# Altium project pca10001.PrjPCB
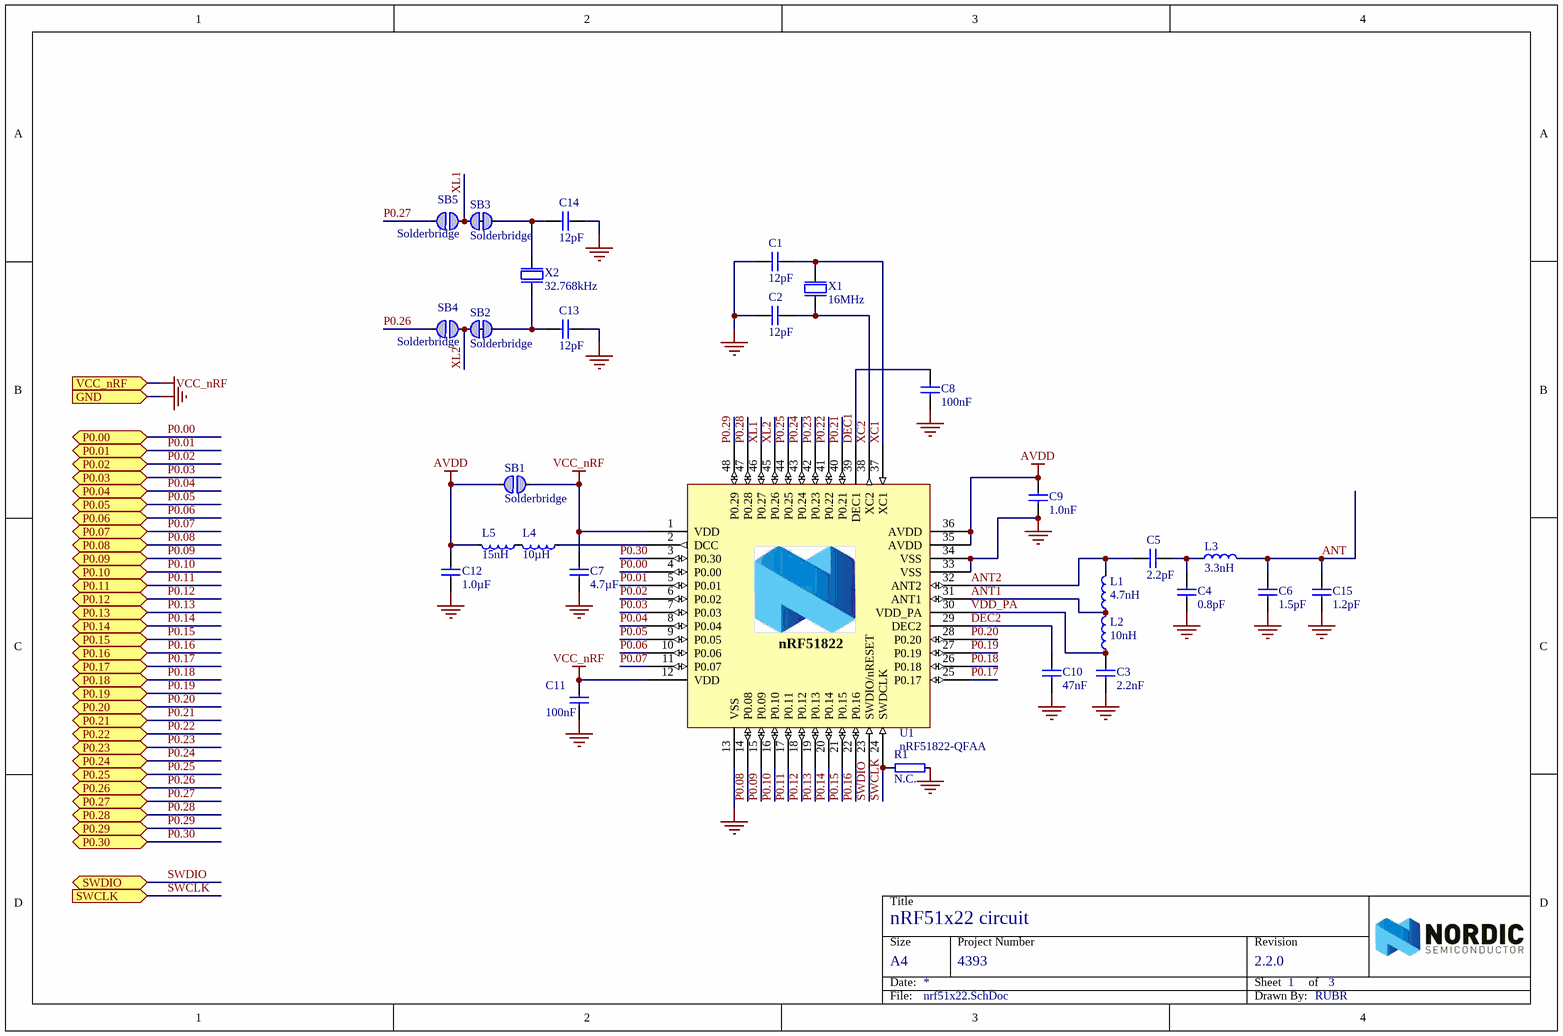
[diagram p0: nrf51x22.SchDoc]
3 sheets, 116 parts. Net scope: flat (ports and power ports of the same name join across sheets).
Board file: 400004.PcbDoc
Sheets:
  nrf51x22.SchDoc
  l-link-ob-sam3u-lqfp.SchDoc
  nrf51x22_ek_interfaces.SchDoc

## Sheet nrf51x22.SchDoc: nRF51x22 circuit
size A4; Revision: 2.2.0; SheetNumber: 1; SheetTotal: 3; DrawnBy: RUBR; ProjectNumber: 4393; PCBRevision: 0101RUBR; DocumentSize: A4; PCAName: PCA10001; PCBNumber: 400004

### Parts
C1  12pF  [CAPC1005X04L]
C2  12pF  [CAPC1005X04L]
C3  2.2nF  [CAPC1005X04L]
C4  0.8pF  [CAPC1005X04L]
C5  2.2pF  [CAPC1005X04L]
C6  1.5pF  [CAPC1005X04L]
C7  4.7µF  [CAPC1608X06L]
C8  100nF  [CAPC1005X04L]
C9  1.0nF  [CAPC1005X04L]
C10  47nF  [CAPC1005X04L]
C11  100nF  [CAPC1005X04L]
C12  1.0µF  [CAPC1608X06L]
C13  12pF  [CAPC1005X04L]
C14  12pF  [CAPC1005X04L]
C15  1.2pF  [CAPC1005X04L]
L1  4.7nH  [INDC1005X04L]
L2  10nH  [INDC1005X04L]
L3  3.3nH  [INDC1005X04L]
L4  10µH  [INDC1608X06L]
L5  15nH  [INDC1005X04L]
R1  N.C.  [RESC1005X04L]
SB1  Solderbridge  [Solderbridge]  (no BOM)
SB2  Solderbridge  [Solderbridge_Shorted]  (net tie, no BOM)
SB3  Solderbridge  [Solderbridge_Shorted]  (net tie, no BOM)
SB4  Solderbridge  [Solderbridge]  (no BOM)
SB5  Solderbridge  [Solderbridge]  (no BOM)
U1  nRF51822-QFAA  [QFN40P600X600X90-48N]
X1  16MHz  [BT-XTAL_2520]
X2  32.768kHz  [FC-135]

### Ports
GND (in), P0.00 (bidir), P0.01 (bidir), P0.02 (bidir), P0.03 (bidir), P0.04 (bidir), P0.05 (bidir), P0.06 (bidir), P0.07 (bidir), P0.08 (bidir), P0.09 (bidir), P0.10 (bidir), P0.11 (bidir), P0.12 (bidir), P0.13 (bidir), P0.14 (bidir), P0.15 (bidir), P0.16 (bidir), P0.17 (bidir), P0.18 (bidir), P0.19 (bidir), P0.20 (bidir), P0.21 (bidir), P0.22 (bidir), P0.23 (bidir), P0.24 (bidir), P0.25 (bidir), P0.26 (bidir), P0.27 (bidir), P0.28 (bidir), P0.29 (bidir), P0.30 (bidir), SWCLK (in), SWDIO (bidir), VCC_nRF (in)

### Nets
AVDD: C9.1 C12.2 L5.2 SB1.2 U1.35(AVDD) U1.36(AVDD)
GND: C1.2 C2.2 C3.2 C4.2 C6.2 C7.2 C8.2 C9.2 C10.2 C11.2 C12.1 C13.2 C14.2 C15.2 R1.1 U1.13(VSS) U1.33(VSS) U1.34(VSS) U1.49 X1.2(GND) X1.4(GND) ; port GND
VCC_nRF: C7.1 C11.1 SB1.1 U1.1(VDD) U1.12(VDD) ; port VCC_nRF
ANT: C6.1 C15.1 L3.2
ANT1: L1.1 L2.2 U1.31(ANT1)
ANT2: C5.1 L1.2 U1.32(ANT2)
DEC1: C8.1 U1.39(DEC1)
DEC2: C10.1 U1.29(DEC2)
P0.00: U1.4(P0.00) ; port P0.00
P0.01: U1.5(P0.01) ; port P0.01
P0.02: U1.6(P0.02) ; port P0.02
P0.03: U1.7(P0.03) ; port P0.03
P0.04: U1.8(P0.04) ; port P0.04
P0.05: U1.9(P0.05) ; port P0.05
P0.06: U1.10(P0.06) ; port P0.06
P0.07: U1.11(P0.07) ; port P0.07
P0.08: U1.14(P0.08) ; port P0.08
P0.09: U1.15(P0.09) ; port P0.09
P0.10: U1.16(P0.10) ; port P0.10
P0.11: U1.17(P0.11) ; port P0.11
P0.12: U1.18(P0.12) ; port P0.12
P0.13: U1.19(P0.13) ; port P0.13
P0.14: U1.20(P0.14) ; port P0.14
P0.15: U1.21(P0.15) ; port P0.15
P0.16: U1.22(P0.16) ; port P0.16  [project net BUTTON0]
P0.17: U1.25(P0.17) ; port P0.17  [project net BUTTON1]
P0.18: U1.26(P0.18) ; port P0.18  [project net LED0]
P0.19: U1.27(P0.19) ; port P0.19  [project net LED1]
P0.20: U1.28(P0.20) ; port P0.20
P0.21: U1.40(P0.21) ; port P0.21
P0.22: U1.41(P0.22) ; port P0.22
P0.23: U1.42(P0.23) ; port P0.23
P0.24: U1.43(P0.24) ; port P0.24
P0.25: U1.44(P0.25) ; port P0.25
P0.26: SB4.2 ; port P0.26
P0.27: SB5.2 ; port P0.27
P0.28: U1.47(P0.28) ; port P0.28
P0.29: U1.48(P0.29) ; port P0.29
P0.30: U1.3(P0.30) ; port P0.30
SWCLK: R1.2 U1.24(SWDCLK) ; port SWCLK
SWDIO: U1.23(SWDIO/nRESET) ; port SWDIO
VDD_PA: C3.1 L2.1 U1.30(VDD_PA)
XC1: C1.1 U1.37(XC1) X1.1(inp)
XC2: C2.1 U1.38(XC2) X1.3(out)
XL1: SB3.2 SB5.1 U1.46(P0.27)
XL2: SB2.2 SB4.1 U1.45(P0.26)
NetC4_1: C4.1 C5.2 L3.1
NetC13_1: C13.1 SB2.1 X2.1(inp)
NetC14_1: C14.1 SB3.1 X2.2(out)
NetL4_1: L4.1 U1.2(DCC)
NetL4_2: L4.2 L5.1

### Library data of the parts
C1 C2 C13 C14 = C0402-12p: Capacitor, NP0, ±2%; Note: 50V; Artikkelnr Noca: 20029159
C3 = C0402-2n2: Capacitor, X7R, ±10%; Note: 50V; Artikkelnr Noca: 20039221
C4 = C0402-0.8p: Capacitor, NP0, ±5%; Note: 50V; Artikkelnr Noca: 20029147
C5 = C0402-2.2p: Capacitor, NP0, ±0.1pF; Note: 50V; Artikkelnr Noca: 20029145
C6 = C0402-1.5p: Capacitor, NP0, ±0.1pF; Note: 50V; Artikkelnr Noca: 20029139
C7 = C0603-4µ7: Capacitor, X5R, ±10%; Note: 6.3V; Artikkelnr Noca: 20069060
C8 C11 = C0402-100n: Capacitor, X7R, ±10%; Note: 16V; Artikkelnr Noca: 20039200
C9 = C0402-1n0: Capacitor, X7R, ±10%; Note: 50V; Artikkelnr Noca: 20039223
C10 = C0402-47n: Capacitor, X7R, ±10%; Note: Chip Cap 10%; Artikkelnr Noca: 20039389
C12 = C0603-1µ0: Capacitor, X7R, ±10%; Note: 16V; Artikkelnr Noca: 20039335
C15 = C0402-1.2p: Capacitor, NP0, ±0.1pF; Note: 50V; Artikkelnr Noca: 20029157
L1 = L0402-4n7: Inductor, 160mA, ±0.1nH; Manufacturer: Murata; Manufacturer Part Number: LQP15MN4N7B02D; Note: High frequency chip inductor ±5%; Artikkelnr Noca: 33029164
L2 = L0402-10n: Inductor, 100mA, ±2%; Manufacturer: Murata; Manufacturer Part Number: LQP15MN10NG02D; Note: High frequency chip inductor ±5%; Artikkelnr Noca: 33029425
L3 = L0402-3n3: Inductor, 190mA, ±0.1nH; Manufacturer: Murata; Manufacturer Part Number: LQP15MN3N3B02D; Note: High frequency chip inductor ±5%; Artikkelnr Noca: 33029369
L4 = L0603-10µ: Inductor, 80mA, ±10%; Manufacturer: Taiyo Yuden; Manufacturer Part Number: LBMF1608T100K; 2nd source part number: 178-6105; Note: LBMF1608T100K 10µH 80mA 0603; Artikkelnr Noca: 33029314
L5 = L0402-15n: Inductor, 320mA, ±5%; Manufacturer: Taiyo Yuden; Manufacturer Part Number: HK100515NJ-T; 2nd source part number: 658-1328; Note: High frequency chip inductor ±10%; Artikkelnr Noca: 33029323
R1 = R0402-N.C.: Not mounted; Note: Chip Res; Artikkelnr Noca: N.A.
SB1 SB4 SB5 = Solderbridge: Artikkelnr Noca: N.A.
SB2 SB3 = Solderbridge Shorted: Shorted Solderbridge; Artikkelnr Noca: N.A.
U1 = nRF51822-QFAA-XLR2.4: Multi-protocol Bluetooth Low Energy and 2.4GHz proprietary system-on-chip; Manufacturer: Nordic Semiconductor; Manufacturer Part Number: nRF51822-QFAAGx; Note: nRF51822 - QFN48 6x6 0.4mm pitch; Artikkelnr Noca: 15079242
X1 = NX2520SA-16MHZ-STD-CSW-5: XTAL SMD 2520, 16MHz, 8pF, ±15ppm; Manufacturer: NDK; Note: XTAL SMD 16.000MHz; Artikkelnr Noca: 22019192
X2 = XTAL_FC-135 32.768k: EPSON TOYOCOM - FC-135 32.768KHZ ±20PPM,9.0PF - CRYSTAL, SM, WATCH; 2nd source part number: 127-8037; Note: XTAL SMD 32.768kHz, 3215; Artikkelnr Noca: 22019091

## Sheet l-link-ob-sam3u-lqfp.SchDoc: J-Link-OB-SAM3U LQPF100
size A3; Revision: 2.0.0; SheetNumber: 2; SheetTotal: 3; DrawnBy: RUBR; ProjectNumber: 4393; PCAName: PCA10001; PCBRevision: 0101RUBR; DocumentSize: A3; PCBNumber: 400004
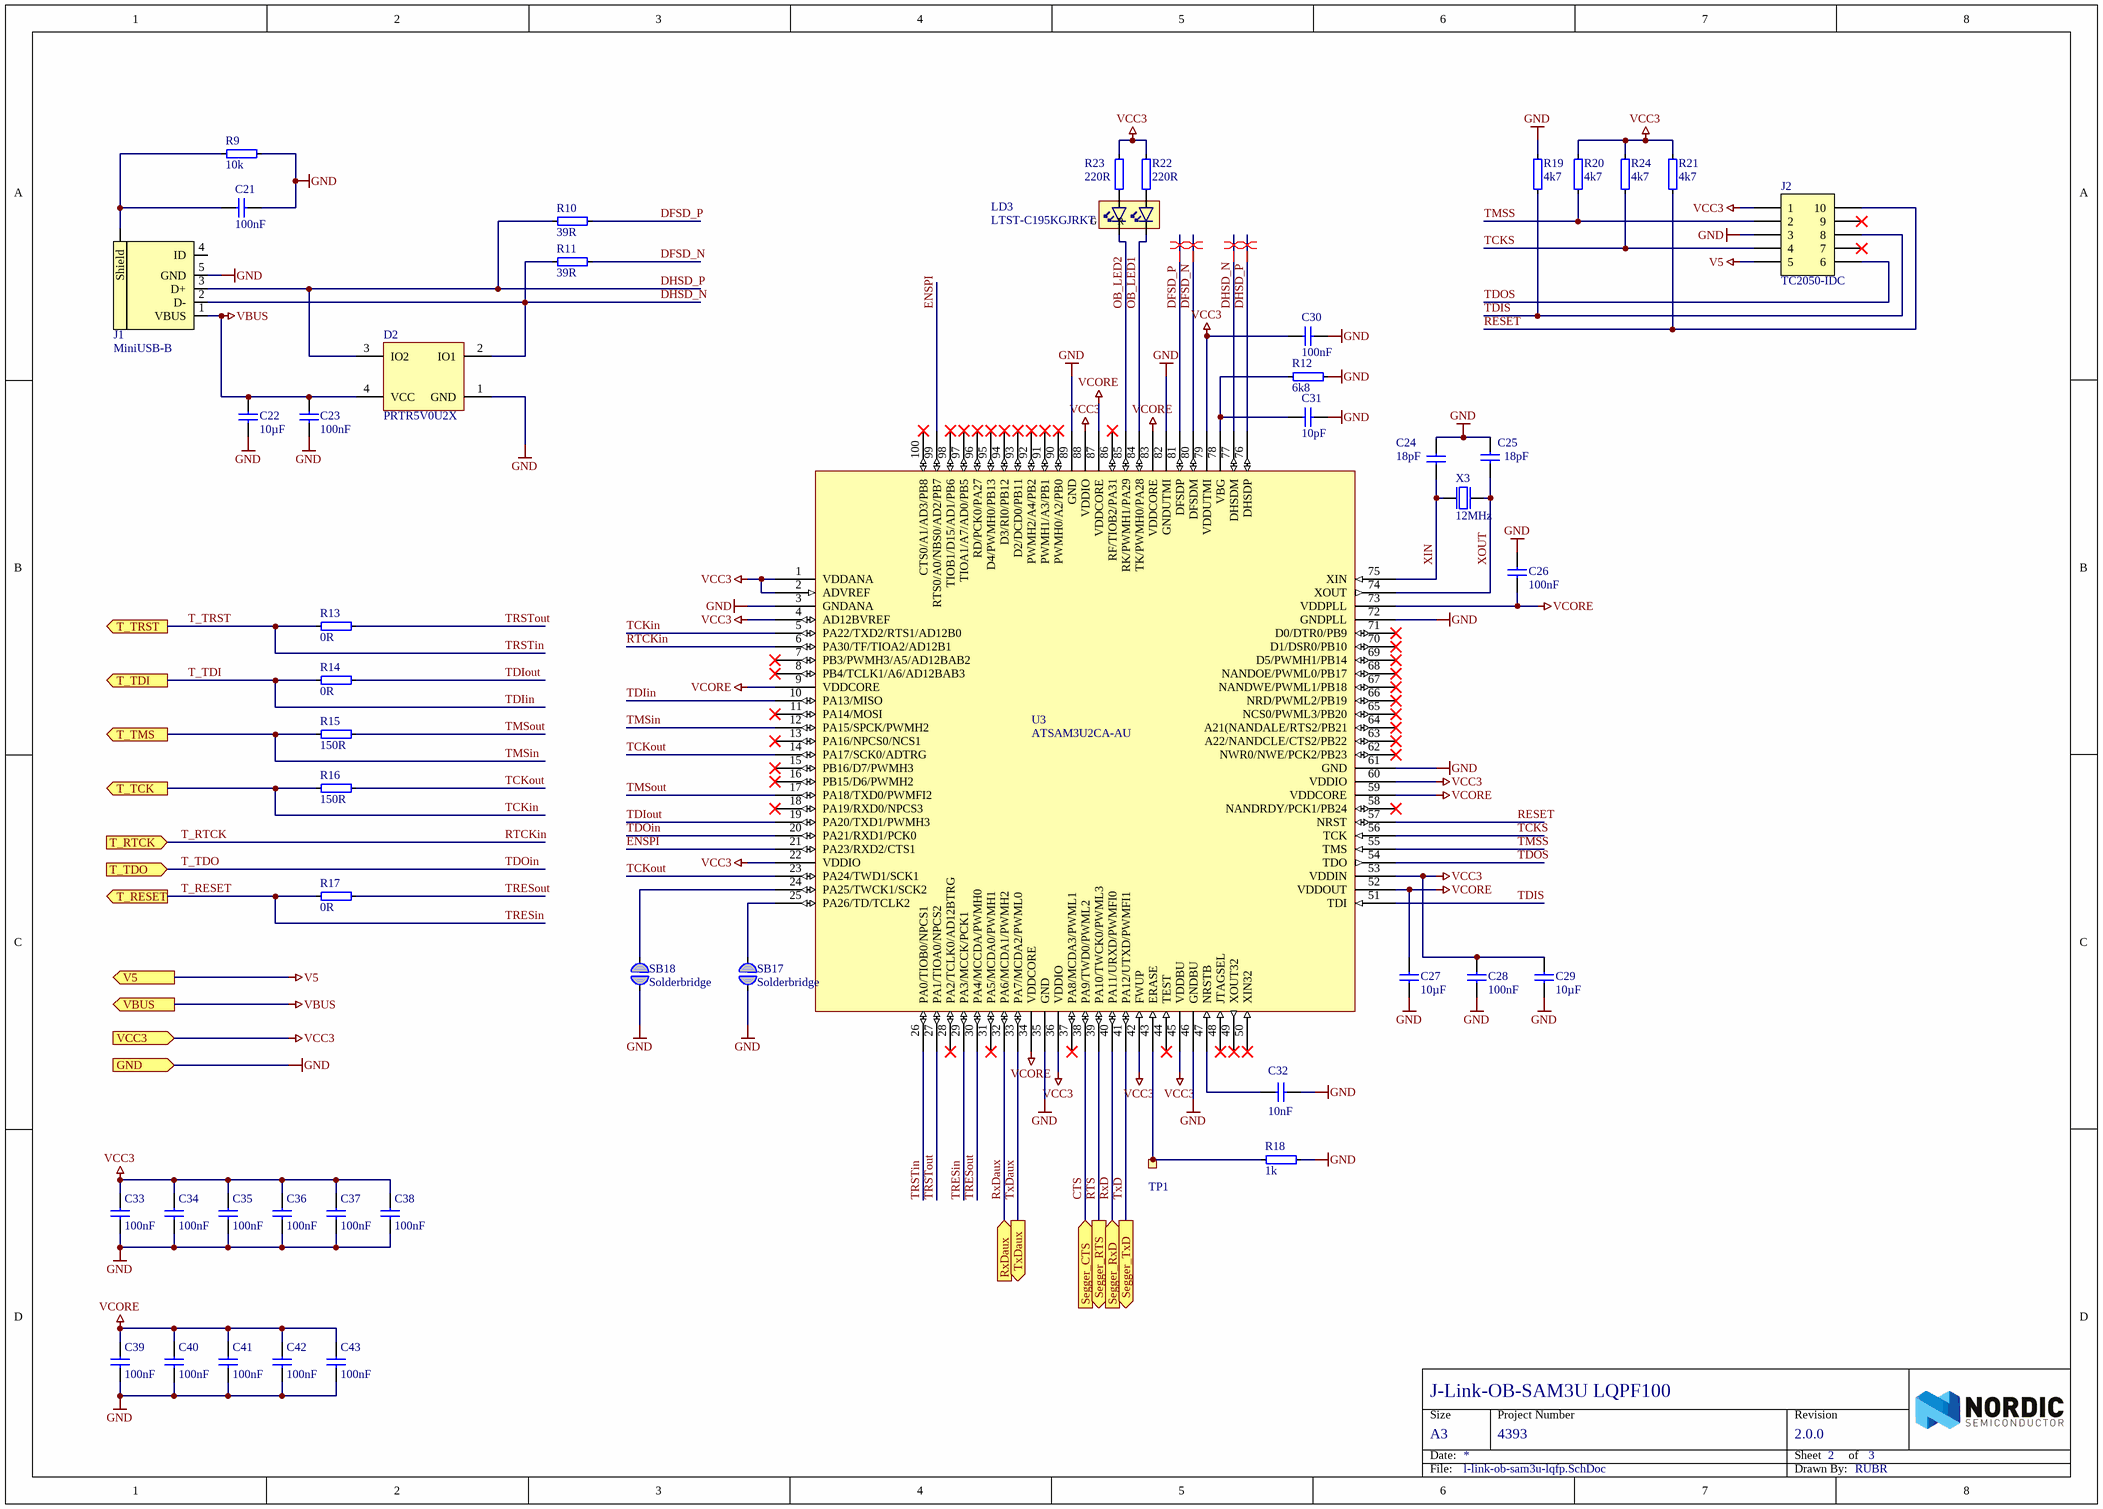
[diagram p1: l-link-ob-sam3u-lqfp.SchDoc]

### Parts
C21  100nF  [CAPC1005X04L]
C22  10µF  [CAPC1608X06L]
C23  100nF  [CAPC1005X04L]
C24  18pF  [CAPC1005X04L]
C25  18pF  [CAPC1005X04L]
C26  100nF  [CAPC1005X04L]
C27  10µF  [CAPC1608X06L]
C28  100nF  [CAPC1005X04L]
C29  10µF  [CAPC1608X06L]
C30  100nF  [CAPC1005X04L]
C31  10pF  [CAPC1005X04L]
C32  10nF  [CAPC1005X04L]
C33  100nF  [CAPC1005X04L]
C34  100nF  [CAPC1005X04L]
C35  100nF  [CAPC1005X04L]
C36  100nF  [CAPC1005X04L]
C37  100nF  [CAPC1005X04L]
C38  100nF  [CAPC1005X04L]
C39  100nF  [CAPC1005X04L]
C40  100nF  [CAPC1005X04L]
C41  100nF  [CAPC1005X04L]
C42  100nF  [CAPC1005X04L]
C43  100nF  [CAPC1005X04L]
D2  PRTR5V0U2X  [SOT190P230X110-4L]
J1  MiniUSB-B  [UX60SC-MB-5ST]
J2  TC2050-IDC  [TC2050-IDC-NLFP]  (no BOM)
LD3  LTST-C195KGJRKT  [LED_DUAL_0606]
R9  10k  [RESC1005X04L]
R10  39R  [RESC1005X04L]
R11  39R  [RESC1005X04L]
R12  6k8  [RESC1005X04L]
R13  0R  [RESC1005X04L]
R14  0R  [RESC1005X04L]
R15  150R  [RESC1005X04L]
R16  150R  [RESC1005X04L]
R17  0R  [RESC1005X04L]
R18  1k  [RESC1005X04L]
R19  4k7  [RESC1005X04L]
R20  4k7  [RESC1005X04L]
R21  4k7  [RESC1005X04L]
R22  220R  [RESC1005X04L]
R23  220R  [RESC1005X04L]
R24  4k7  [RESC1005X04L]
SB17  Solderbridge  [Solderbridge]  (no BOM)
SB18  Solderbridge  [Solderbridge]  (no BOM)
TP1  1.5mm,SMD  [TP_SMD_1.5mmX1.5mm]  (value not drawn)  (no BOM)
U3  ATSAM3U2CA-AU  [TSQFP50P1600X1600X160-100N]
X3  12MHz  [BT-XTAL_3225]

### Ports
GND (in), RxDaux (in), Segger_CTS (in), Segger_RTS (out), Segger_RxD (in), Segger_TxD (out), T_RESET (out), T_RTCK (in), T_TCK (out), T_TDI (out), T_TDO (in), T_TMS (out), T_TRST (out), TxDaux (out), V5 (out), VBUS (out), VCC3 (in)

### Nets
GND: C21.1 C22.1 C23.1 C24.2 C25.2 C26.2 C27.1 C28.1 C29.1 C30.1 C31.1 C32.1 C33.1 C34.1 C35.1 C36.1 C37.1 C38.1 C39.1 C40.1 C41.1 C42.1 C43.1 D2.1(GND) J1.5(GND) J2.3 R9.1 R12.1 R18.1 R19.2 SB17.2 SB18.2 U3.3(GNDANA) U3.35(GND) U3.46(GNDBU) U3.61(GND) U3.72(GNDPLL) U3.82(GNDUTMI) U3.89(GND) X3.2(GND) X3.4(GND) ; port GND
V5: C22.2 C23.2 D2.4(VCC) J1.1(VBUS) J2.5 ; port V5, port VBUS  [also labelled VBUS]
VCC3: C28.2 C29.2 C30.2 C33.2 C34.2 C35.2 C36.2 C37.2 C38.2 J2.1 R20.2 R21.2 R22.2 R23.2 R24.2 U3.1(VDDANA) U3.2(ADVREF) U3.4(AD12BVREF) U3.22(VDDIO) U3.36(VDDIO) U3.42(FWUP) U3.45(VDDBU) U3.53(VDDIN) U3.60(VDDIO) U3.79(VDDUTMI) U3.88(VDDIO) ; port VCC3
VCORE: C26.1 C27.2 C39.2 C40.2 C41.2 C42.2 C43.2 U3.9(VDDCORE) U3.34(VDDCORE) U3.52(VDDOUT) U3.59(VDDCORE) U3.73(VDDPLL) U3.83(VDDCORE) U3.87(VDDCORE)
CTS: U3.38(PA9/TWD0/PWML2) ; port Segger_CTS
DFSD_N: R11.1 U3.80(DFSDM)
DFSD_P: R10.1 U3.81(DFSDP)
DHSD_N: D2.2(IO1) J1.2(D-) R11.2 U3.77(DHSDM)
DHSD_P: D2.3(IO2) J1.3(D+) R10.2 U3.76(DHSDP)
ENSPI: U3.21(PA23/RXD2/CTS1) U3.99(RTS0/A0/NBS0/AD2/PB7)
OB_LED1: LD3.4(C1) U3.84(TK/PWMH0/PA28)
OB_LED2: LD3.3(C2) U3.85(RK/PWMH1/PA29)
RESET: J2.10 R21.1 U3.57(NRST)
RTCKin: U3.6(PA30/TF/TIOA2/AD12B1) ; port T_RTCK  [also labelled T_RTCK]
RTS: U3.39(PA10/TWCK0/PWML3) ; port Segger_RTS
RxD: U3.40(PA11/URXD/PWMFI0) ; port Segger_RxD
RxDaux: U3.32(PA6/MCDA1/PWMH2) ; port RxDaux
T_RESET: R17.2 U3.29(PA3/MCCK/PCK1) ; port T_RESET  [also labelled TRESin]
T_TDI: R14.2 U3.10(PA13/MISO) ; port T_TDI  [also labelled TDIin]
T_TDO: U3.20(PA21/RXD1/PCK0) ; port T_TDO  [also labelled TDOin]
T_TRST: R13.2 U3.26(PA0/TIOB0/NPCS1) ; port T_TRST  [also labelled TRSTin]
TCKin: R16.2 U3.5(PA22/TXD2/RTS1/AD12B0) ; port T_TCK
TCKout: R16.1 U3.14(PA17/SCK0/ADTRG) U3.23(PA24/TWD1/SCK1)
TCKS: J2.4 R24.1 U3.56(TCK)
TDIout: R14.1 U3.19(PA20/TXD1/PWMH3)
TDIS: J2.8 R19.1 U3.51(TDI)
TDOS: J2.6 U3.54(TDO)
TMSin: R15.2 U3.12(PA15/SPCK/PWMH2) ; port T_TMS
TMSout: R15.1 U3.17(PA18/TXD0/PWMFI2)
TMSS: J2.2 R20.1 U3.55(TMS)
TRESout: R17.1 U3.30(PA4/MCCDA/PWMH0)
TRSTout: R13.1 U3.27(PA1/TIOA0/NPCS2)
TxD: U3.41(PA12/UTXD/PWMFI1) ; port Segger_TxD
TxDaux: U3.33(PA7/MCDA2/PWML0) ; port TxDaux
XIN: C24.1 U3.75(XIN) X3.3(out)
XOUT: C25.1 U3.74(XOUT) X3.1(inp)
NetC21_2: C21.2 J1.6(Shield) R9.2
NetC31_2: C31.2 R12.2 U3.78(VBG)
NetC32_2: C32.2 U3.47(NRSTB)
NetLD3_1: LD3.1(A2) R23.1
NetLD3_2: LD3.2(A1) R22.1
NetR18_2: R18.2 TP1.1 U3.43(ERASE)
NetSB17_1: SB17.1 U3.25(PA26/TD/TCLK2)
NetSB18_1: SB18.1 U3.24(PA25/TWCK1/SCK2)

Not connected (* = marked no-connect by the designer): J1 4(ID); J2 7* 9*; U3 7(PB3/PWMH3/A5/AD12BAB2)* 8(PB4/TCLK1/A6/AD12BAB3)* 11(PA14/MOSI)* 13(PA16/NPCS0/NCS1)* 15(PB16/D7/PWMH3)* 16(PB15/D6/PWMH2)* 18(PA19/RXD0/NPCS3)* 28(PA2/TCLK0/AD12BTRG)* 31(PA5/MCDA0/PWMH1)* 37(PA8/MCDA3/PWML1)* 44(TEST)* 48(JTAGSEL)* 49(XOUT32)* 50(XIN32)* 58(NANDRDY/PCK1/PB24)* 62(NWR0/NWE/PCK2/PB23)* 63(A22/NANDCLE/CTS2/PB22)* 64(A21(NANDALE/RTS2/PB21)* 65(NCS0/PWML3/PB20)* 66(NRD/PWML2/PB19)* 67(NANDWE/PWML1/PB18)* 68(NANDOE/PWML0/PB17)* 69(D5/PWMH1/PB14)* 70(D1/DSR0/PB10)* 71(D0/DTR0/PB9)* 86(RF/TIOB2/PA31)* 90(PWMH0/A2/PB0)* 91(PWMH1/A3/PB1)* 92(PWMH2/A4/PB2)* 93(D2/DCD0/PB11)* 94(D3/RI0/PB12)* 95(D4/PWMH0/PB13)* 96(RD/PCK0/PA27)* 97(TIOA1/A7/AD0/PB5)* 98(TIOB1/D15/AD1/PB6)* 100(CTS0/A1/AD3/PB8)*

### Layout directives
differential pair: DFSD_N, DFSD_P, DHSD_N, DHSD_P

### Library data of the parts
C21 C23 C26 C28 C30 C33-C43 = C0402-100n: as C8 on sheet nrf51x22
C22 C27 C29 = C0603-10µ: Capacitor, X5R, ±10%; Note: 6.3V; Artikkelnr Noca: 20039252
C24 C25 = C0402-18p: Capacitor, NP0, ±5%; Note: 50V; Artikkelnr Noca: 20029209
C31 = C0402-10p: Capacitor, NP0, ±2%; 2nd source part number: 185-6064; Note: 50V; Artikkelnr Noca: 20029260
C32 = C0402-10n: Capacitor, X7R, ±10%; Note: 16V; Artikkelnr Noca: 20039166
D2 = PRTR5V0U2X: Ultra low capacitance double rail-to-rail ESD protection diode; Manufacturer: NXP; 2nd source part number: 152-4157; Artikkelnr Noca: 10069015
J1 = Hirose UX60SC-MB-5ST: Hirose MiniUSB-B-SMT; Manufacturer Part Number: UX60SC-MB-5ST(80); 2nd source part number: 798-UX60SCMB5ST01; Artikkelnr Noca: 55029014
J2 = TC2050-IDC-NLFP: CBL PLUG-OF-NAILS 10-PIN; Manufacturer: Tag-Connect LLC; Artikkelnr Noca: N.A.
LD3 = LTST-C195KGJRKT: Avago, HSMF-A203 Bi-Color LED; Manufacturer: Lite-On Inc; 2nd source part number: 859-LTST-C195KGJRKT; Note: HSMF-A203- xxxxx GaP Red GaP Emerald Green; Artikkelnr Noca: 13019145
R9 = R0402-10k: Resistor, ±1%, 0.063W; Note: Chip Res 1%; Artikkelnr Noca: 27049097
R10 R11 = R0402-39R: Resistor, ±1%, 0.063W; Note: Chip Res 1%; Artikkelnr Noca: 27049039
R12 = R0402-6k8: Resistor, ±1%, 0.063W; Note: Chip Res 1%; Artikkelnr Noca: 27049093
R13 R14 R17 = R0402-0R: Resistor, ±5%, 0.063W; Note: Chip Res 5%; Artikkelnr Noca: 27049000
R15 R16 = R0402-150: Resistor, ±1%, 0.063W; Note: Chip Res 1%; Artikkelnr Noca: 27049053
R18 = R0402-1k0: Resistor, ±1%, 0.063W; Note: Chip Res 1%; Artikkelnr Noca: 27049073
R19-R21 R24 = R0402-4k7: Resistor, ±1%, 0.063W; Note: Chip Res 1%; Artikkelnr Noca: 27049089
R22 R23 = R0402-220: Resistor, ±1%, 0.063W; Note: Chip Res 1%; Artikkelnr Noca: 27049057
SB17 SB18 = Solderbridge: Artikkelnr Noca: N.A.
TP1 = TP_SMD_1.5MM: Regular Plated, 1.5mm hole; Manufacturer: Nordic Semiconductor; Artikkelnr Noca: N.A.
U3 = ATSAM3U2CA-AU: IC MCU 32bit 128kB flash 100LQFP; Manufacturer: Atmel; 2nd source part number: 184-1662; Artikkelnr Noca: 15019073
X3 = XTAL SMD 12MHz (3225): XTAL SMD 3225, 12MHz, 18pF, ±30ppm; Manufacturer: TXC Corporation; Manufacturer Part Number: 7M-12.000MAAJ-T; 2nd source part number: 184-2056; Note: XTAL SMD 12.000MHz; Artikkelnr Noca: 22019166

## Sheet nrf51x22_ek_interfaces.SchDoc: nRF51x22 EK Interfaces
size A4; Revision: 2.0.0; SheetNumber: 3; SheetTotal: 3; DrawnBy: RUBR; ProjectNumber: 4393; PCBRevision: 0101RUBR; DocumentSize: A4; PCAName: PCA10001; PCBNumber: 400004
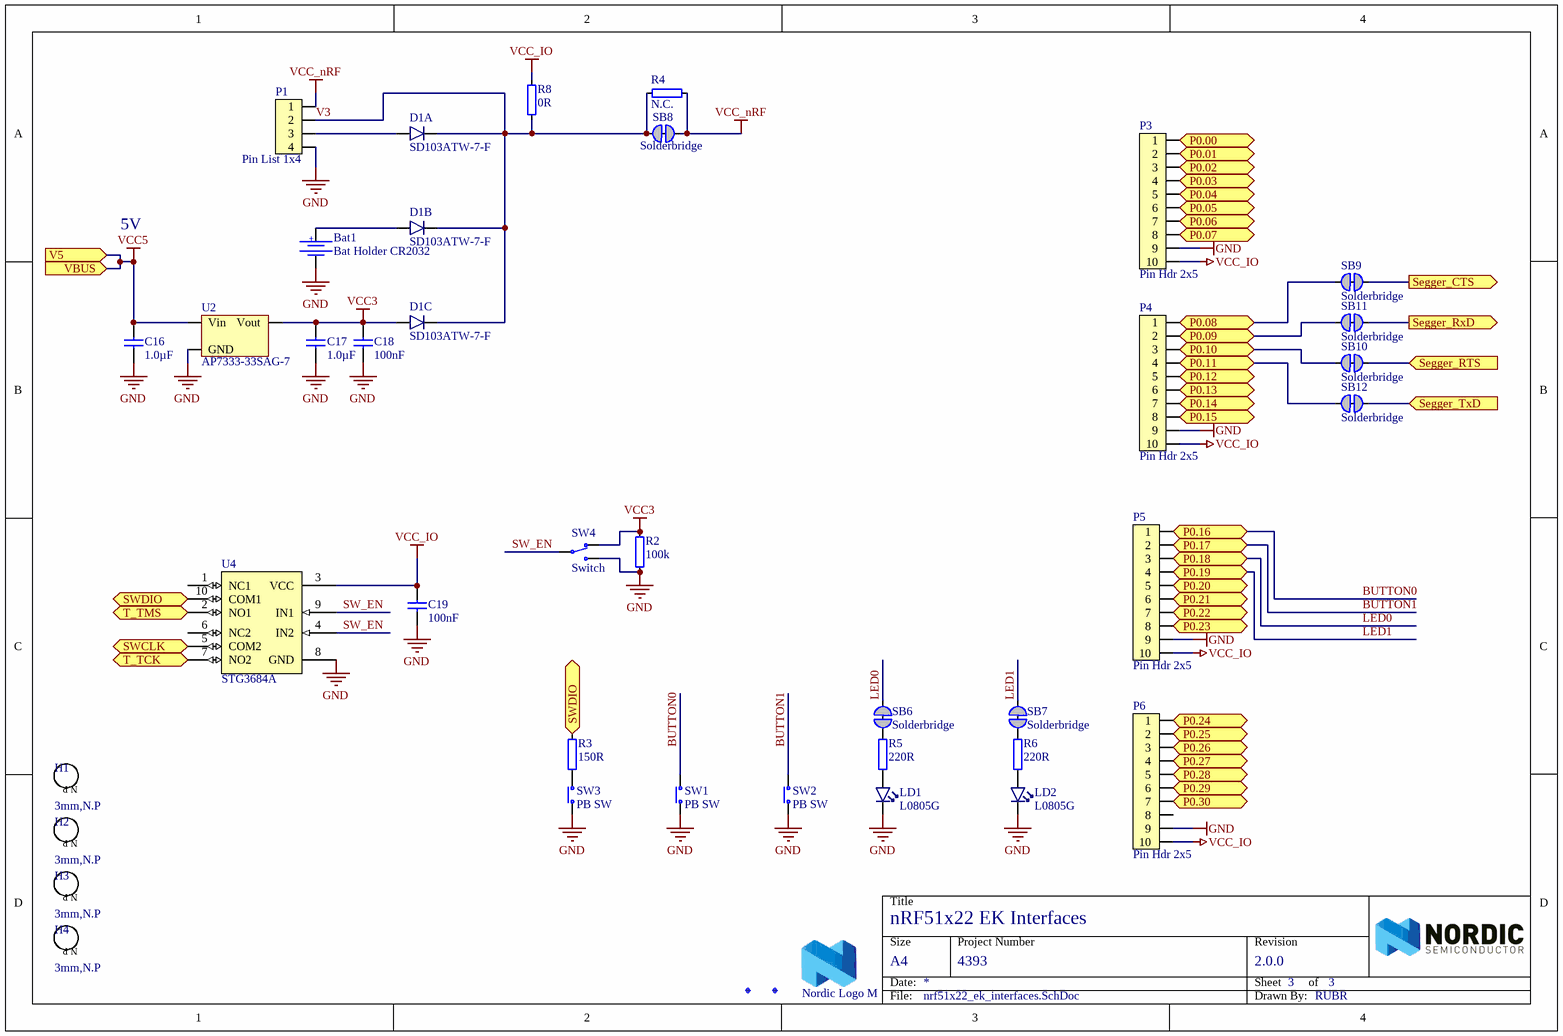
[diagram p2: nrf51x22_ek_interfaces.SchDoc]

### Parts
Bat1  Bat Holder CR2032  [CR2032_HOLDER_SMD]
C16  1.0µF  [CAPC1608X06L]
C17  1.0µF  [CAPC1608X06L]
C18  100nF  [CAPC1005X04L]
C19  100nF  [CAPC1005X04L]
D1  SD103ATW-7-F  [SOT-363]  (parts A,B,C of 3)
Fid1  Fiducial mark  [Fiducial]  (value not drawn)
Fid2  Fiducial mark  [Fiducial]  (value not drawn)
H1  3mm,N.P  [HOLE_NP_3MM]  (no BOM)
H2  3mm,N.P  [HOLE_NP_3MM]  (no BOM)
H3  3mm,N.P  [HOLE_NP_3MM]  (no BOM)
H4  3mm,N.P  [HOLE_NP_3MM]  (no BOM)
LD1  L0805G  [LED_0805]
LD2  L0805G  [LED_0805]
LOGO1  Nordic Logo M  [NORDIC_LOGO_M]  (no BOM)
P1  Pin List 1x4  [LIST_1x4_SMD]
P3  Pin Hdr 2x5  [Molex 15-91-2100]
P4  Pin Hdr 2x5  [Molex 15-91-2100]
P5  Pin Hdr 2x5  [Molex 15-91-2100]
P6  Pin Hdr 2x5  [Molex 15-91-2100]
R2  100k  [RESC1005X04L]
R3  150R  [RESC1005X04L]
R4  N.C.  [RESC1005X04L]
R5  220R  [RESC1005X04L]
R6  220R  [RESC1005X04L]
R8  0R  [RESC1005X04L]
SB6  Solderbridge  [Solderbridge_Shorted]  (net tie, no BOM)
SB7  Solderbridge  [Solderbridge_Shorted]  (net tie, no BOM)
SB8  Solderbridge  [Solderbridge_Shorted]  (net tie, no BOM)
SB9  Solderbridge  [Solderbridge_Shorted]  (net tie, no BOM)
SB10  Solderbridge  [Solderbridge_Shorted]  (net tie, no BOM)
SB11  Solderbridge  [Solderbridge_Shorted]  (net tie, no BOM)
SB12  Solderbridge  [Solderbridge_Shorted]  (net tie, no BOM)
SW1  PB SW  [ALPS_SKHUxxx010_WO_GND]
SW2  PB SW  [ALPS_SKHUxxx010_WO_GND]
SW3  PB SW  [ALPS_SKHUxxx010_WO_GND]
SW4  Switch  [CJS-120xA]
U2  AP7333-33SAG-7  [SOT-23A]
U4  STG3684A  [QFN40P180X140X55-10N]

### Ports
P0.00 (bidir), P0.01 (bidir), P0.02 (bidir), P0.03 (bidir), P0.04 (bidir), P0.05 (bidir), P0.06 (bidir), P0.07 (bidir), P0.08 (bidir), P0.09 (bidir), P0.10 (bidir), P0.11 (bidir), P0.12 (bidir), P0.13 (bidir), P0.14 (bidir), P0.15 (bidir), P0.16 (bidir), P0.17 (bidir), P0.18 (bidir), P0.19 (bidir), P0.20 (bidir), P0.21 (bidir), P0.22 (bidir), P0.23 (bidir), P0.24 (bidir), P0.25 (bidir), P0.26 (bidir), P0.27 (bidir), P0.28 (bidir), P0.29 (bidir), P0.30 (bidir), Segger_CTS (out), Segger_RTS (in), Segger_RxD (out), Segger_TxD (in), SWCLK (in), SWDIO (bidir), T_TCK (out), T_TMS (out), V5 (in), VBUS (in)

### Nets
GND: Bat1.2 C16.1 C17.1 C18.1 C19.1 LD1.1(C) LD2.1(C) P1.4 P3.9 P4.9 P5.9 P6.9 R2.1 SW1.2(COM) SW2.2(COM) SW3.2(COM) SW4.3(N.O) U2.3(GND) U4.8(GND)
VCC3: C17.2 C18.2 D1.4(A3) R2.2 SW4.1(N.C) U2.2(Vout)
VCC5: C16.2 U2.1(Vin) ; port V5, port VBUS  [project net V5]
VCC_IO: C19.2 P3.10 P4.10 P5.10 P6.10 R8.2 U4.3(VCC)
VCC_nRF: P1.1 R4.1 SB8.2
BUTTON0: P5.1 SW1.1(N.O) ; port P0.16
BUTTON1: P5.2 SW2.1(N.O) ; port P0.17
CTS: SB9.1 ; port Segger_CTS
LED0: P5.3 SB6.1 ; port P0.18
LED1: P5.4 SB7.1 ; port P0.19
P0.00: P3.1 ; port P0.00
P0.01: P3.2 ; port P0.01
P0.02: P3.3 ; port P0.02
P0.03: P3.4 ; port P0.03
P0.04: P3.5 ; port P0.04
P0.05: P3.6 ; port P0.05
P0.06: P3.7 ; port P0.06
P0.07: P3.8 ; port P0.07
P0.08: P4.1 SB9.2 ; port P0.08
P0.09: P4.2 SB11.2 ; port P0.09
P0.10: P4.3 SB10.2 ; port P0.10
P0.11: P4.4 SB12.2 ; port P0.11
P0.12: P4.5 ; port P0.12
P0.13: P4.6 ; port P0.13
P0.14: P4.7 ; port P0.14
P0.15: P4.8 ; port P0.15
P0.20: P5.5 ; port P0.20
P0.21: P5.6 ; port P0.21
P0.22: P5.7 ; port P0.22
P0.23: P5.8 ; port P0.23
P0.24: P6.1 ; port P0.24
P0.25: P6.2 ; port P0.25
P0.26: P6.3 ; port P0.26
P0.27: P6.4 ; port P0.27
P0.28: P6.5 ; port P0.28
P0.29: P6.6 ; port P0.29
P0.30: P6.7 ; port P0.30
RTS: SB10.1 ; port Segger_RTS
RxD: SB11.1 ; port Segger_RxD
SW_EN: SW4.2(COM) U4.4(IN2) U4.9(IN1)
SWCLK: U4.5(COM2) ; port SWCLK
SWDIO: R3.2 U4.10(COM1) ; port SWDIO
TCKin: U4.7(NO2) ; port T_TCK
TMSin: U4.2(NO1) ; port T_TMS
TxD: SB12.1 ; port Segger_TxD
V3: D1.1(C1) D1.2(C2) D1.3(C3) P1.2 R4.2 R8.1 SB8.1
NetBat1_1: Bat1.1 D1.5(A2)
NetD1_6: D1.6(A1) P1.3
NetLD1_2: LD1.2(A) R5.1
NetLD2_2: LD2.2(A) R6.1
NetR3_1: R3.1 SW3.1(N.O)
NetR5_2: R5.2 SB6.2
NetR6_2: R6.2 SB7.2

Not connected (* = marked no-connect by the designer): P6 8; U4 1(NC1) 6(NC2)

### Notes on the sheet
- 5V

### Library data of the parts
Bat1 = Bat Holder CR2032 SMD: Manufacturer: Keystone; Manufacturer Part Number: 3002; 2nd source part number: 69-525-27; Artikkelnr Noca: 34019038
C16 C17 = C0603-1µ0: Capacitor, X5R, ±10%; Note: 10V; Artikkelnr Noca: 20039205
C18 C19 = C0402-100n: as C8 on sheet nrf51x22
D1 = SD103ATW-7-F: Surface Mount Schottky Barrier Diode Array; Manufacturer: Diodes Incorporated; 2nd source part number: 177-3507; Artikkelnr Noca: 10029109
Fid1 Fid2 = Fid-Mark: Artikkelnr Noca: N.A.
H1-H4 = Hole_3MM_NP: Regular Non-Plated, 3mm hole; Manufacturer: Nordic Semiconductor; Artikkelnr Noca: N.A.
LD1 LD2 = SML-210PT: LED, SMD, 0805, GREEN; Manufacturer: ROHM; Manufacturer Part Number: SML-210PTT86; Note: 4 mcd @ 20 mA; Artikkelnr Noca: 13019123
LOGO1 = Nordic Logo M: Nordic Logo, medium size; Artikkelnr Noca: N.A.
P1 = Pin List 1x4 SMD: Pin List 1x4, 2.54mm (100mil); Artikkelnr Noca: N.A.
P3-P6 = Pin Header 2x5 SMD: Pin Header 2x5, 2.54mm (100mil) SMD; Manufacturer: Molex; Artikkelnr Noca: 55019194
R2 = R0402-100k: Resistor, ±1%, 0.063W; Note: Chip Res 1%; Artikkelnr Noca: 27049121
R3 = R0402-150: as R15 on sheet l-link-ob-sam3u-lqfp
R4 = R0402-N.C.: as R1 on sheet nrf51x22
R5 R6 = R0402-220: as R22 on sheet l-link-ob-sam3u-lqfp
R8 = R0402-0R: as R13 on sheet l-link-ob-sam3u-lqfp
SB6-SB12 = Solderbridge Shorted: as SB2 on sheet nrf51x22
SW1-SW3 = ALPS_SKHUALE010: ALPS - SKHUALE010 - Tactile Switch, SPNO, SMD, 6.5x6.2x2.5mm; 2nd source part number: 688-SKHUALE010; Artikkelnr Noca: 50019001
SW4 = CJS-1200TA: SMD slide Switch (ON-ON); Manufacturer: Copal Electronics Inc; Artikkelnr Noca: N.A.
U2 = AP7333-33SAG-7: 300mA, Low Quiescent Current, Fast Transient Low Dropout Linear Regulator; Manufacturer: Diodes Incorporated; Artikkelnr Noca: 17039216
U4 = STG3684AU: Low voltage 0.5 ohm max dual SPDT switch with break-before-make; Manufacturer: STMicroelectronics; Manufacturer Part Number: STG3684AUTR; 2nd source part number: 511-STG3684AUTR; Artikkelnr Noca: N.A.

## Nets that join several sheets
GND: nrf51x22 (21 pins), l-link-ob-sam3u-lqfp (41 pins), nrf51x22_ek_interfaces (19 pins)
V5: l-link-ob-sam3u-lqfp (5 pins), nrf51x22_ek_interfaces (C16.2 U2.1)
VCC3: l-link-ob-sam3u-lqfp (26 pins), nrf51x22_ek_interfaces (6 pins)
VCC_nRF: nrf51x22 (5 pins), nrf51x22_ek_interfaces (P1.1 R4.1 SB8.2)
BUTTON0: nrf51x22 (U1.22), nrf51x22_ek_interfaces (P5.1 SW1.1)
BUTTON1: nrf51x22 (U1.25), nrf51x22_ek_interfaces (P5.2 SW2.1)
CTS: l-link-ob-sam3u-lqfp (U3.38), nrf51x22_ek_interfaces (SB9.1)
LED0: nrf51x22 (U1.26), nrf51x22_ek_interfaces (P5.3 SB6.1)
LED1: nrf51x22 (U1.27), nrf51x22_ek_interfaces (P5.4 SB7.1)
P0.00: nrf51x22 (U1.4), nrf51x22_ek_interfaces (P3.1)
P0.01: nrf51x22 (U1.5), nrf51x22_ek_interfaces (P3.2)
P0.02: nrf51x22 (U1.6), nrf51x22_ek_interfaces (P3.3)
P0.03: nrf51x22 (U1.7), nrf51x22_ek_interfaces (P3.4)
P0.04: nrf51x22 (U1.8), nrf51x22_ek_interfaces (P3.5)
P0.05: nrf51x22 (U1.9), nrf51x22_ek_interfaces (P3.6)
P0.06: nrf51x22 (U1.10), nrf51x22_ek_interfaces (P3.7)
P0.07: nrf51x22 (U1.11), nrf51x22_ek_interfaces (P3.8)
P0.08: nrf51x22 (U1.14), nrf51x22_ek_interfaces (P4.1 SB9.2)
P0.09: nrf51x22 (U1.15), nrf51x22_ek_interfaces (P4.2 SB11.2)
P0.10: nrf51x22 (U1.16), nrf51x22_ek_interfaces (P4.3 SB10.2)
P0.11: nrf51x22 (U1.17), nrf51x22_ek_interfaces (P4.4 SB12.2)
P0.12: nrf51x22 (U1.18), nrf51x22_ek_interfaces (P4.5)
P0.13: nrf51x22 (U1.19), nrf51x22_ek_interfaces (P4.6)
P0.14: nrf51x22 (U1.20), nrf51x22_ek_interfaces (P4.7)
P0.15: nrf51x22 (U1.21), nrf51x22_ek_interfaces (P4.8)
P0.20: nrf51x22 (U1.28), nrf51x22_ek_interfaces (P5.5)
P0.21: nrf51x22 (U1.40), nrf51x22_ek_interfaces (P5.6)
P0.22: nrf51x22 (U1.41), nrf51x22_ek_interfaces (P5.7)
P0.23: nrf51x22 (U1.42), nrf51x22_ek_interfaces (P5.8)
P0.24: nrf51x22 (U1.43), nrf51x22_ek_interfaces (P6.1)
P0.25: nrf51x22 (U1.44), nrf51x22_ek_interfaces (P6.2)
P0.26: nrf51x22 (SB4.2), nrf51x22_ek_interfaces (P6.3)
P0.27: nrf51x22 (SB5.2), nrf51x22_ek_interfaces (P6.4)
P0.28: nrf51x22 (U1.47), nrf51x22_ek_interfaces (P6.5)
P0.29: nrf51x22 (U1.48), nrf51x22_ek_interfaces (P6.6)
P0.30: nrf51x22 (U1.3), nrf51x22_ek_interfaces (P6.7)
RTS: l-link-ob-sam3u-lqfp (U3.39), nrf51x22_ek_interfaces (SB10.1)
RxD: l-link-ob-sam3u-lqfp (U3.40), nrf51x22_ek_interfaces (SB11.1)
SWCLK: nrf51x22 (R1.2 U1.24), nrf51x22_ek_interfaces (U4.5)
SWDIO: nrf51x22 (U1.23), nrf51x22_ek_interfaces (R3.2 U4.10)
TCKin: l-link-ob-sam3u-lqfp (R16.2 U3.5), nrf51x22_ek_interfaces (U4.7)
TMSin: l-link-ob-sam3u-lqfp (R15.2 U3.12), nrf51x22_ek_interfaces (U4.2)
TxD: l-link-ob-sam3u-lqfp (U3.41), nrf51x22_ek_interfaces (SB12.1)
